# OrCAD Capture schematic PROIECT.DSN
size A
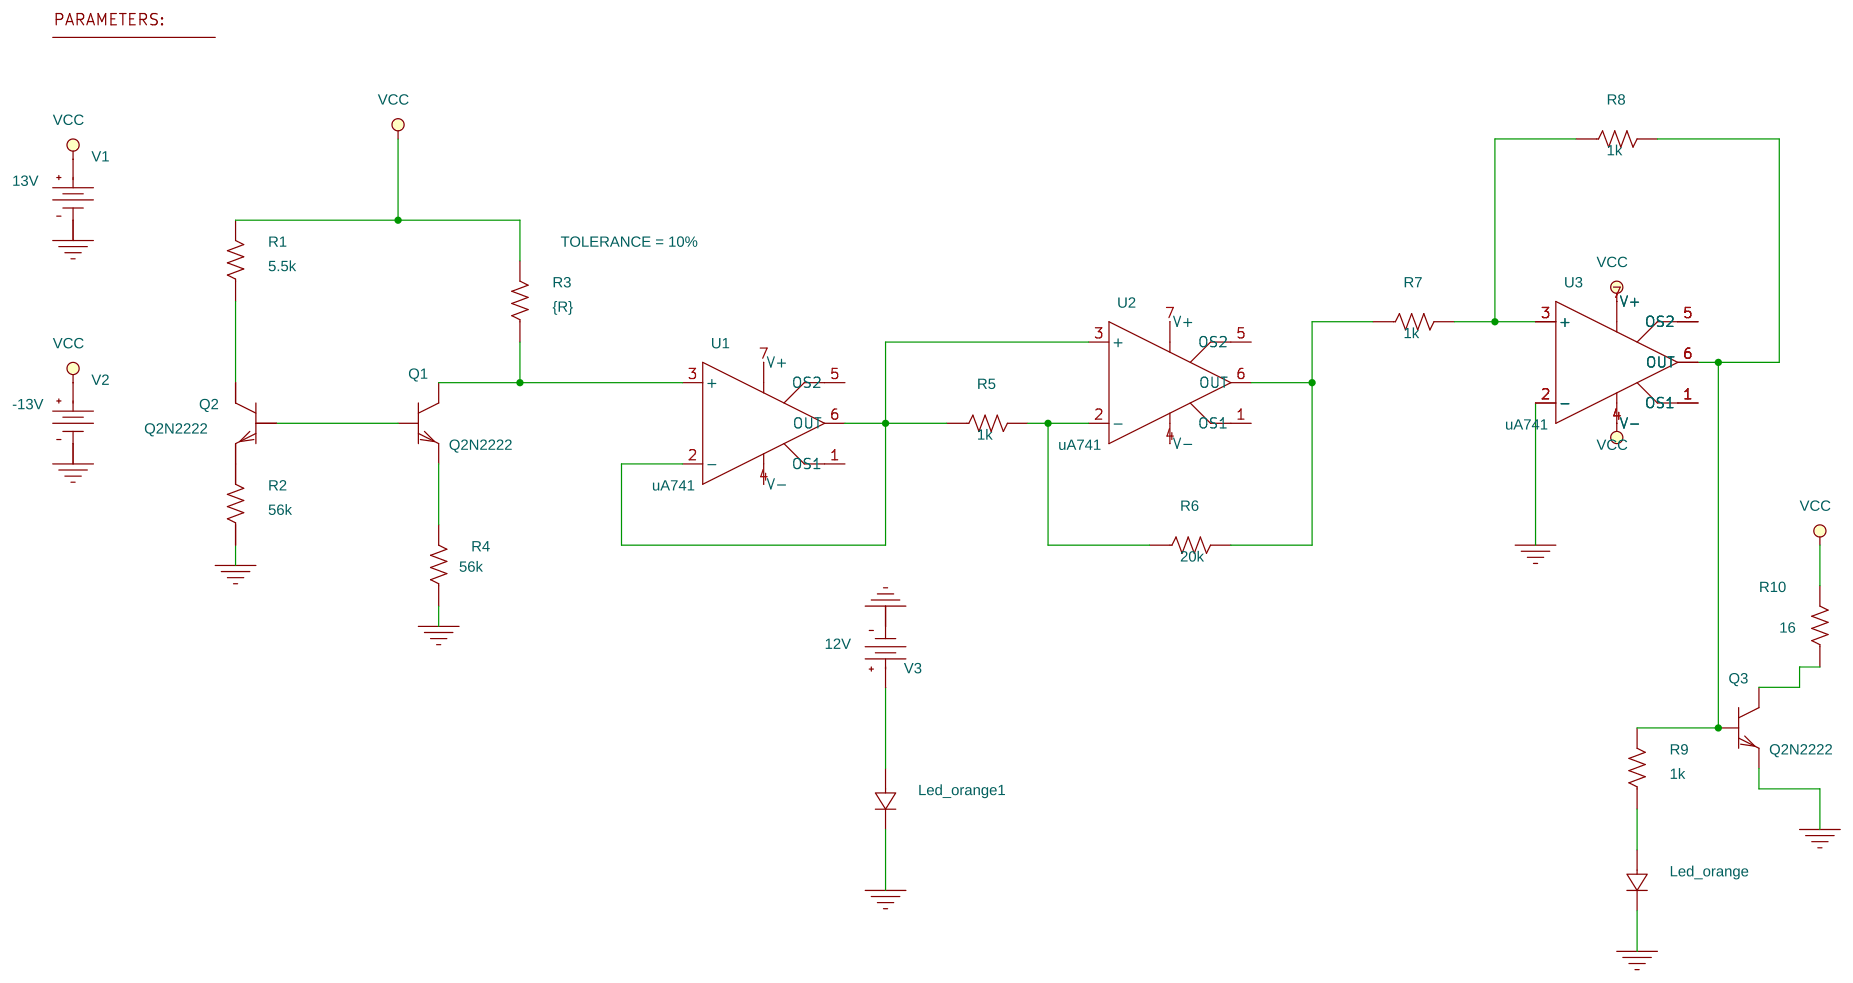
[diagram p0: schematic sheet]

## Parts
1  PARAM
Led_orange  Dbreak
Led_orange1  Dbreak
Q1  Q2N2222  [TO18]
Q2  Q2N2222  [TO18]
Q3  Q2N2222  [TO18]
R1  5.5k  [AXRC05]
R2  56k  [AXRC05]
R3  {R}  [AXRC05]
R4  56k  [AXRC05]
R5  1k  [AXRC05]
R6  20k  [AXRC05]
R7  1k  [AXRC05]
R8  1k  [AXRC05]
R9  1k  [AXRC05]
R10  16  [AXRC05]
U1  uA741  [DIP1008W300L450]
U2  uA741  [DIP1008W300L450]
U3  uA741  [DIP1008W300L450]
V1  VDC
V2  VDC
V3  VDC

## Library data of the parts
1 = PARAM: R: 1k
Led_orange Led_orange1 = Dbreak
Q1-Q3 = Q2N2222
R1 R2 R4-R10 = R
R3 = R: TOLERANCE: 10%
U1-U3 = uA741
V1 = VDC: DC: 13V
V2 = VDC: DC: -13V
V3 = VDC: DC: 12V

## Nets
-VCC: U3.4(V-) V2.0(+)
VCC: R1.2 R3.2 R10.2 U3.7(V+) V1.0(+)
0: Led_orange.1(2) Led_orange1.1(2) Q3.1(e) R2.1 R4.1 U3.2(-) V1.1(-) V2.1(-) V3.1(-)
V+: U1.7(V+) U2.7(V+)
V-: U1.4(V-) U2.4(V-)
N00213: Q1.3(c) R3.1 U1.3(+)
N00225: Q1.2(b) Q2.2(b)
N00238: Q2.3(c) R1.1
N00329: R5.1 U1.2(-) U1.6(OUT) U2.3(+)
N01229: R5.2 R6.1 U2.2(-)
N01283: R6.2 R7.1 U2.6(OUT)
N01429: R7.2 R8.1 U3.3(+)
N01446: Q3.2(b) R8.2 R9.2 U3.6(OUT)
N01823: Led_orange.0(1) R9.1
N02814: Q1.1(e) R4.2
N04516: Q3.3(c) R10.1
N05844: Q2.1(e) R2.2
N07619: Led_orange1.0(1) V3.0(+)

Not connected (* = marked no-connect by the designer): U1 1(OS1) 5(OS2); U2 1(OS1) 5(OS2); U3 1(OS1) 5(OS2)
